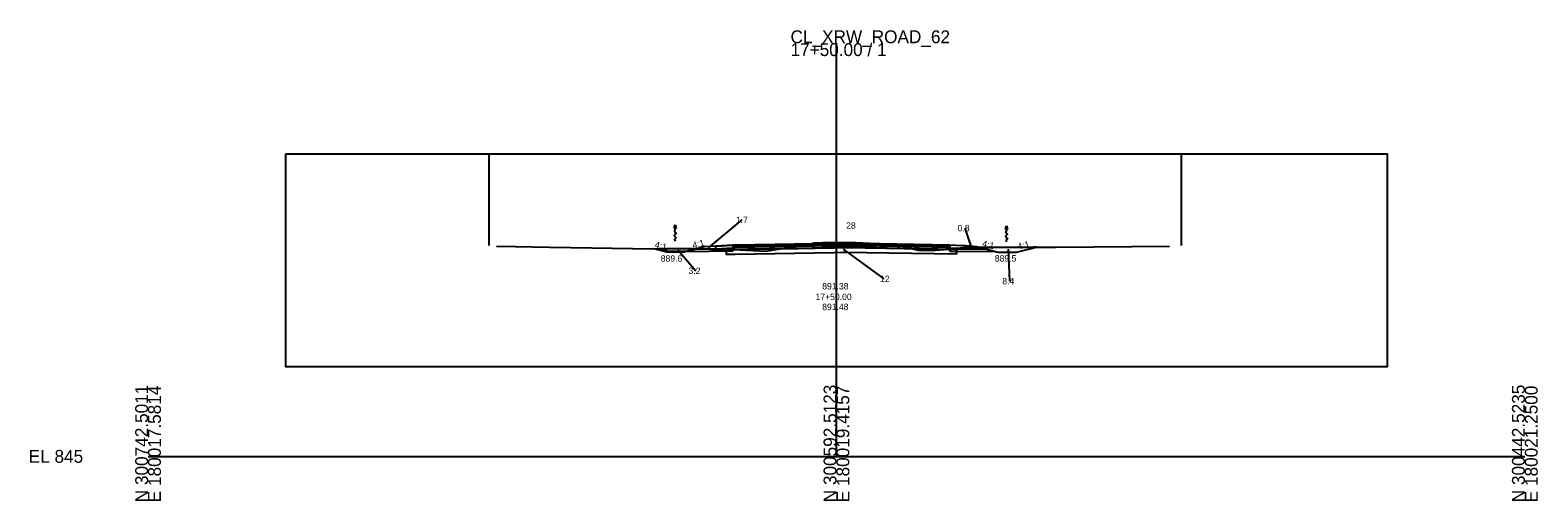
# Model space of a CAD drawing. Extents: x -26 to 180171, y 490 to 300744.
# Drawn here: x -25.7 to 302.8, y 2490.3 to 2592.8 of the extents above; entities that cross this region are included whole.
import ezdxf

# ---------------------------------------------------------------- set-up
doc = ezdxf.new("R2010")
doc.units = 0
for name, color, linetype in [('CL_P_Construction', 7, 'Continuous'), ('CM_Corridor_Top_Mesh', 7, 'Continuous'), ('Default', 7, 'Continuous'), ('DR_P_Ditch', 7, 'Continuous'), ('DT_P_Contour_Major', 7, 'Continuous'), ('DT_P_Contour_Minor', 7, 'Continuous'), ('DT_P_Spot_Elevations', 7, 'Continuous'), ('DT_P_TIN_Hull', 7, 'Continuous'), ('DT_P_Triangles', 7, 'Continuous'), ('DT_P_Void', 7, 'Continuous'), ('DT_X_Void', 7, 'Continuous'), ('GK_Patterns', 7, 'Continuous'), ('MD_P_Surface_Aggregate_Base', 7, 'Continuous'), ('MD_P_Surface_Asphalt_Concrete_Base', 7, 'Continuous'), ('MD_P_Surface_Asphalt_Concrete_Surface_Course', 7, 'Continuous'), ('MD_P_Surface_Chemically_Stabalized_Subgrade', 7, 'Continuous'), ('MT_P_CL_40', 7, 'Continuous'), ('PV_P_Saw_Cut_Line', 7, 'Continuous'), ('RD_P_Fence', 7, 'Continuous'), ('RW_P_Const_Limits', 7, 'Continuous'), ('RW_P_Esmt_LA', 7, 'Continuous'), ('SC_Scratch1', 7, 'Continuous'), ('SV_X_Control_Cells_Found', 7, 'Continuous'), ('SV_X_Text_Name', 7, 'Continuous'), ('XS_X_Ground_Line', 7, 'Continuous')]:
    doc.layers.add(name, color=color, linetype=linetype)

msp = doc.modelspace()

# ---------------------------------------------------------------- linework, layer by layer
at = {"layer": 'CL_P_Construction'}
msp.add_lwpolyline([(151.6, 2546.41), (151.57, 2546.41), (151.56, 2546.41), (151.5, 2546.41), (149.53, 2546.37), (127.91, 2546.01), (127.46, 2546), (127.46, 2545.9), (127.91, 2545.9), (149.53, 2546.27), (151.5, 2546.3), (151.56, 2546.3), (151.57, 2546.3), (151.6, 2546.3), (151.62, 2546.3), (151.64, 2546.3), (151.72, 2546.3), (174.69, 2545.94), (174.69, 2546.04), (151.72, 2546.41), (151.64, 2546.41), (151.62, 2546.41), (151.6, 2546.41)], dxfattribs=at)
at = {"layer": 'CM_Corridor_Top_Mesh'}
for p, q in [((112.95, 2544.56), (116.95, 2544.56)), ((185.25, 2544.5), (189.25, 2544.5))]:
    msp.add_line(p, q, dxfattribs=at)
at = {"layer": 'DR_P_Ditch'}
for points in [[(127.46, 2546), (127.46, 2545.33), (123.69, 2545.13), (123.69, 2545.8), (127.46, 2546)], [(151.6, 2545.97), (151.57, 2545.97), (151.56, 2545.97), (151.5, 2545.97), (149.53, 2545.94), (127.91, 2545.57), (127.46, 2545.56), (127.46, 2545.06), (127.91, 2545.07), (149.53, 2545.44), (151.5, 2545.47), (151.56, 2545.47), (151.57, 2545.47), (151.6, 2545.47), (151.62, 2545.47), (151.64, 2545.47), (151.72, 2545.47), (174.69, 2545.1), (174.69, 2545.6), (151.72, 2545.97), (151.64, 2545.97), (151.62, 2545.97), (151.6, 2545.97)], [(177.31, 2545.89), (174.69, 2546.04), (174.69, 2545.37), (177.31, 2545.22), (178.19, 2545.17), (178.19, 2545.84), (177.31, 2545.89)]]:
    msp.add_lwpolyline(points, dxfattribs=at)
at = {"layer": 'DT_P_Contour_Major'}
for points in [[(123.69, 2545.13), (123.69, 2545.8)], [(123.69, 2545.13), (125.96, 2545.25), (125.96, 2545.04), (125.96, 2544.04)], [(178.19, 2545.17), (177.31, 2545.22), (176.19, 2545.29), (176.19, 2544.08)], [(178.19, 2545.17), (178.19, 2545.84)]]:
    msp.add_lwpolyline(points, dxfattribs=at)
at = {"layer": 'DT_P_Contour_Minor'}
msp.add_lwpolyline([(151.6, 2545.47), (151.57, 2545.47), (151.56, 2545.47), (151.5, 2545.47), (149.53, 2545.44), (127.91, 2545.07), (125.96, 2545.04), (125.96, 2544.04), (127.91, 2544.07), (149.53, 2544.44), (151.5, 2544.47), (151.56, 2544.47), (151.57, 2544.47), (151.6, 2544.47), (151.62, 2544.47), (151.64, 2544.47), (151.72, 2544.47), (176.19, 2544.08), (176.19, 2545.08), (151.72, 2545.47), (151.64, 2545.47), (151.62, 2545.47), (151.6, 2545.47)], dxfattribs=at)
at = {"layer": 'DT_P_Spot_Elevations'}
for points in [[(127.46, 2546), (127.46, 2545.33), (125.58, 2545.23), (123.69, 2545.13), (123.69, 2545.8), (121.18, 2545.62)], [(180.59, 2545.66), (178.19, 2545.84), (178.19, 2545.17), (177.31, 2545.22), (176.42, 2545.27), (174.69, 2545.37), (174.69, 2546.04)]]:
    msp.add_lwpolyline(points, dxfattribs=at)
at = {"layer": 'DT_P_Triangles'}
msp.add_lwpolyline([(151.6, 2546.3), (151.57, 2546.3), (151.56, 2546.3), (151.5, 2546.3), (149.53, 2546.27), (127.91, 2545.9), (127.46, 2545.9), (127.46, 2545.56), (127.91, 2545.57), (149.53, 2545.94), (151.5, 2545.97), (151.56, 2545.97), (151.57, 2545.97), (151.6, 2545.97), (151.62, 2545.97), (151.64, 2545.97), (151.72, 2545.97), (174.69, 2545.6), (174.69, 2545.94), (151.72, 2546.3), (151.64, 2546.3), (151.62, 2546.3), (151.6, 2546.3)], dxfattribs=at)
at = {"layer": 'DT_P_Void'}
msp.add_lwpolyline([(30, 2565.91), (270, 2565.91), (270, 2519.48), (30, 2519.48)], close=True, dxfattribs=at)
at = {"layer": 'DT_X_Void'}
for p, q in [((150, 2500), (150, 2590)), ((0, 2500), (150, 2500)), ((150, 2500), (300, 2500))]:
    msp.add_line(p, q, dxfattribs=at)
at = {"layer": 'GK_Patterns'}
for p, q in [((110.17, 2545.26), (112.95, 2544.56)), ((121.18, 2545.62), (116.95, 2544.56)), ((180.59, 2545.66), (185.25, 2544.5)), ((189.25, 2544.5), (193.59, 2545.58))]:
    msp.add_line(p, q, dxfattribs=at)
at = {"layer": 'MD_P_Surface_Asphalt_Concrete_Base'}
msp.add_lwpolyline([(147.08, 2546.48), (147.08, 2545.62), (151.64, 2545.63), (154.19, 2545.65), (158.71, 2545.45), (160.87, 2545.37), (160.87, 2546.22), (158.71, 2546.31), (154.19, 2546.51), (151.64, 2546.49), (147.08, 2546.48)], dxfattribs=at)
at = {"layer": 'MD_P_Surface_Asphalt_Concrete_Surface_Course'}
for p, q in [((114.62, 2549.61), (114.84, 2550.41)), ((115.05, 2549.61), (114.62, 2549.61)), ((114.84, 2550.41), (115.05, 2549.61)), ((186.84, 2549.41), (187.06, 2550.21)), ((187.27, 2549.41), (186.84, 2549.41)), ((187.06, 2550.21), (187.27, 2549.41))]:
    msp.add_line(p, q, dxfattribs=at)
for points in [[(114.84, 2549.61), (114.84, 2549.58), (114.76, 2549.25), (114.69, 2549.04), (115.06, 2548.62), (114.64, 2548.13), (115.06, 2547.57), (114.83, 2547.46), (114.84, 2546.91)], [(187.05, 2549.42), (187.05, 2549.38), (186.98, 2549.05), (186.91, 2548.85), (187.27, 2548.42), (186.86, 2547.94), (187.27, 2547.38), (187.05, 2547.26), (187.06, 2546.71)]]:
    msp.add_spline(points, degree=3, dxfattribs=at)
at = {"layer": 'MD_P_Surface_Chemically_Stabalized_Subgrade'}
msp.add_lwpolyline([(151.6, 2545.47), (151.57, 2545.47), (151.56, 2545.47), (151.5, 2545.47), (149.53, 2545.44), (125.96, 2545.04), (125.96, 2544.04), (127.91, 2544.07), (149.53, 2544.44), (151.5, 2544.47), (151.56, 2544.47), (151.57, 2544.47), (151.6, 2544.47), (151.62, 2544.47), (151.64, 2544.47), (151.72, 2544.47), (176.19, 2544.08), (176.19, 2545.08), (151.72, 2545.47), (151.64, 2545.47), (151.62, 2545.47), (151.6, 2545.47)], dxfattribs=at)
at = {"layer": 'MT_P_CL_40'}
msp.add_lwpolyline([(127.46, 2546), (127.91, 2546.01), (149.53, 2546.37), (151.5, 2546.41), (151.56, 2546.41), (151.57, 2546.41), (151.6, 2546.41), (151.62, 2546.41), (151.64, 2546.41), (151.72, 2546.41), (174.69, 2546.04)], dxfattribs=at)
at = {"layer": 'PV_P_Saw_Cut_Line'}
for points in [[(127.46, 2546), (123.69, 2545.8), (121.18, 2545.62)], [(180.59, 2545.66), (178.19, 2545.84), (177.31, 2545.89), (174.69, 2546.04)]]:
    msp.add_lwpolyline(points, dxfattribs=at)
at = {"layer": 'RD_P_Fence'}
msp.add_lwpolyline([(147.08, 2546.48), (147.08, 2545.62), (151.64, 2545.63), (154.19, 2545.65), (158.71, 2545.45), (160.87, 2545.37), (160.87, 2546.22), (158.71, 2546.31), (154.19, 2546.51), (151.64, 2546.49), (147.08, 2546.48)], dxfattribs=at)
at = {"layer": 'RW_P_Const_Limits'}
for points in [[(123.69, 2545.8), (121.18, 2545.62)], [(178.19, 2545.84), (180.59, 2545.66)]]:
    msp.add_lwpolyline(points, dxfattribs=at)
at = {"layer": 'RW_P_Esmt_LA'}
msp.add_lwpolyline([(147.08, 2546.48), (151.64, 2546.49), (154.19, 2546.51), (158.71, 2546.31), (160.87, 2546.22)], dxfattribs=at)
at = {"layer": 'SC_Scratch1'}
msp.add_lwpolyline([(75.93, 2545.75), (80.08, 2545.74), (87.57, 2545.54), (96.69, 2545.42), (105.58, 2545.28), (119.4, 2545.21), (129.05, 2545), (134.58, 2544.7), (136.78, 2545.04), (140.21, 2545.57), (141.19, 2545.78), (143.59, 2546.17), (144.67, 2546.32), (145.17, 2546.44), (146.32, 2546.47), (147.08, 2546.48), (150, 2546.48), (151.64, 2546.49), (154.19, 2546.51), (158.71, 2546.31), (160.87, 2546.22), (161.46, 2546.21), (162.82, 2546.19), (164.76, 2545.66), (165.6, 2545.43), (167.43, 2545.01), (168.22, 2544.82), (170.62, 2544.89), (171.55, 2544.92), (174.24, 2545.15), (177.8, 2545.43), (183.36, 2545.51), (192.91, 2545.58), (197.9, 2545.6), (222.58, 2545.81)], dxfattribs=at)
at = {"layer": 'SV_X_Control_Cells_Found'}
for p, q in [((74.27, 2565.95), (74.27, 2545.95)), ((225.15, 2565.95), (225.15, 2545.95))]:
    msp.add_line(p, q, dxfattribs=at)
at = {"layer": 'SV_X_Text_Name'}
for p, q in [((122.12, 2545.43), (129.44, 2551.51)), ((179.4, 2545.6), (178.05, 2549.72)), ((160.87, 2546.22), (160.87, 2545.37)), ((111.29, 2545.25), (113.5, 2544.7)), ((119.4, 2545.21), (111.29, 2545.25)), ((113.5, 2544.7), (117.5, 2544.7)), ((115.42, 2545), (119.36, 2540.42)), ((117.5, 2544.7), (119.41, 2545.18)), ((121.18, 2545.62), (119.53, 2545.21)), ((119.53, 2545.21), (123.69, 2545.17)), ((123.69, 2545.8), (121.18, 2545.62)), ((123.69, 2545.17), (123.69, 2545.8)), ((151.47, 2545.13), (160.31, 2538.66)), ((158.71, 2545.45), (154.19, 2545.65)), ((160.87, 2545.37), (158.71, 2545.45)), ((164.65, 2545.27), (164.65, 2545.27)), ((173.84, 2545.12), (176.19, 2545.08)), ((176.19, 2545.08), (176.19, 2545.29)), ((180.59, 2545.66), (178.19, 2545.84)), ((178.19, 2545.84), (178.19, 2545.43)), ((178.19, 2545.43), (181.34, 2545.48)), ((178.19, 2545.17), (178.19, 2545.43)), ((181.34, 2545.48), (180.59, 2545.66)), ((181.34, 2545.48), (185.25, 2544.5)), ((185.25, 2544.5), (189.25, 2544.5)), ((187.4, 2545.11), (187.73, 2538.18)), ((189.25, 2544.5), (193.59, 2545.58)), ((193.59, 2545.58), (192.91, 2545.58))]:
    msp.add_line(p, q, dxfattribs=at)
for points in [[(147.08, 2546.48), (146.32, 2546.47), (145.17, 2546.44), (144.67, 2546.32), (143.59, 2546.17), (141.19, 2545.78), (140.21, 2545.57), (138.07, 2545.24)], [(154.19, 2545.65), (151.64, 2545.63), (147.08, 2545.62), (147.08, 2546.48)], [(164.65, 2545.27), (166.39, 2545.25), (165.6, 2545.43), (164.76, 2545.66), (162.82, 2546.19), (161.46, 2546.21), (160.87, 2546.22)], [(119.41, 2545.18), (119.4, 2545.21)], [(138.07, 2545.24), (149.17, 2545.43)], [(149.17, 2545.43), (151.35, 2545.47), (151.48, 2545.47)], [(151.48, 2545.47), (162.58, 2545.32)], [(162.58, 2545.32), (164.65, 2545.27)], [(178.19, 2545.43), (177.8, 2545.43), (174.24, 2545.15), (173.84, 2545.12)], [(176.19, 2545.29), (177.31, 2545.22), (178.19, 2545.17)], [(192.91, 2545.58), (183.36, 2545.51), (181.34, 2545.48)]]:
    msp.add_lwpolyline(points, dxfattribs=at)
at = {"layer": 'XS_X_Ground_Line'}
for p, q in [((127.46, 2544.67), (116.95, 2544.56)), ((127.46, 2545.17), (119.5, 2545.09)), ((127.46, 2545.17), (127.46, 2544.67)), ((174.69, 2545.21), (182.74, 2545.13)), ((174.69, 2544.71), (174.69, 2545.21)), ((174.69, 2544.71), (184.83, 2544.61))]:
    msp.add_line(p, q, dxfattribs=at)

# ---------------------------------------------------------------- texts
at = {"layer": 'Default'}
msp.add_text('-', height=0.0001, dxfattribs=at).set_placement((0, 2500))
at = {"layer": 'DT_P_TIN_Hull'}
for s, p in [('891.38', (146.9, 2536.36)), ('17+50.00', (145.45, 2534.05)), ('891.48', (146.9, 2531.85))]:
    msp.add_text(s, height=1.4, dxfattribs=at).set_placement(p)
at = {"layer": 'DT_X_Void'}
for s, p in [('CL_XRW_ROAD_62', (140, 2590)), ('17+50.00 / 1', (140, 2587.2)), ('EL 845', (-26, 2498.6))]:
    msp.add_text(s, height=2.8, dxfattribs=at).set_placement(p)
for s, p in [('N 300742.5011', (0, 2490)), ('E 180017.5814', (2.8, 2490)), ('N 300592.5123', (150, 2490)), ('E 180019.4157', (152.8, 2490)), ('N 300442.5235', (300, 2490)), ('E 180021.2500', (302.8, 2490))]:
    msp.add_text(s, height=2.8, rotation=90, dxfattribs=at).set_placement(p)
at = {"layer": 'MD_P_Surface_Aggregate_Base'}
for rotation, p in [(345.9638, (110.31, 2545.5)), (14.0362, (118.8, 2545.28)), (345.9638, (181.65, 2545.74)), (14.0362, (189.66, 2544.99))]:
    msp.add_text('4:1', height=1.4, rotation=rotation, dxfattribs=at).set_placement(p)
for s, p in [('889.6', (111.72, 2542.41)), ('889.5', (184.52, 2542.43))]:
    msp.add_text(s, height=1.4, dxfattribs=at).set_placement(p)
at = {"layer": 'SV_X_Text_Name'}
for s, p in [('1.7', (128.09, 2550.81)), ('28', (152.12, 2549.58)), ('0.8', (176.42, 2549.02)), ('3.2', (117.77, 2539.72)), ('12', (159.51, 2537.96)), ('8.4', (186.15, 2537.48))]:
    msp.add_text(s, height=1.4, dxfattribs=at).set_placement(p)

doc.saveas('drawing.dxf')
